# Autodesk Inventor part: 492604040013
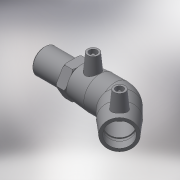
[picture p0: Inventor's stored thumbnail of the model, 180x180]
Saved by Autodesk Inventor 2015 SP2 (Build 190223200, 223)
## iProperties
Created: 2017-06
Part Number: 492604040013
Material: Generic
Description: PLASSON 45° ELBOW TRANSITION MALE 40-1.1/4"
Document SubType Name: Modeling
Designer: KIM
Mass: 196.953 g
Surface Area: 465.484 cm^2
Volume: 196.953 cm^3
Density: 1 g/cm^3
Appearance: Default
Author: KIM
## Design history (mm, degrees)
derived "492604.ipt"
feature "Solid1::492604.ipt"
tag "TaggingFeature1"
body "Solid1"
other parameters: "d2" = 56, "d4" = 27, "d5" = 50.4, "d8" = 168 deg, "d10" = 17.6, "d11" = 5.86667, "d29" = 47, "d30" = 15, "d31" = 37.8, "d34" = 5 deg, "d41" = 4, "d42" = 14, "d43" = 0, "d50" = 26, "d51" = 17.6, "d52" = 45.32, "d54" = 135 deg, "d86" = 25.2, "d87" = 135 deg, "d88" = 108, "d90" = 44, "d91" = 0, "d92" = 44, "d93" = 0, "d101" = 3, "d102" = 0, "d107" = 0.1, "d108" = 29, "d109" = 41.91, "d110" = 36, "d111" = 9, "d112" = 56, "d113" = 29.337, "d114" = 32.4, "d116" = 1.68, "d122" = 0, "d123" = 2.0955, "L_" = 144, "L_1" = 44, "D_" = 29, "A_" = 47, "d_2" = 12, "L_2" = 36, "R_" = 41.91, "D_1" = 56
